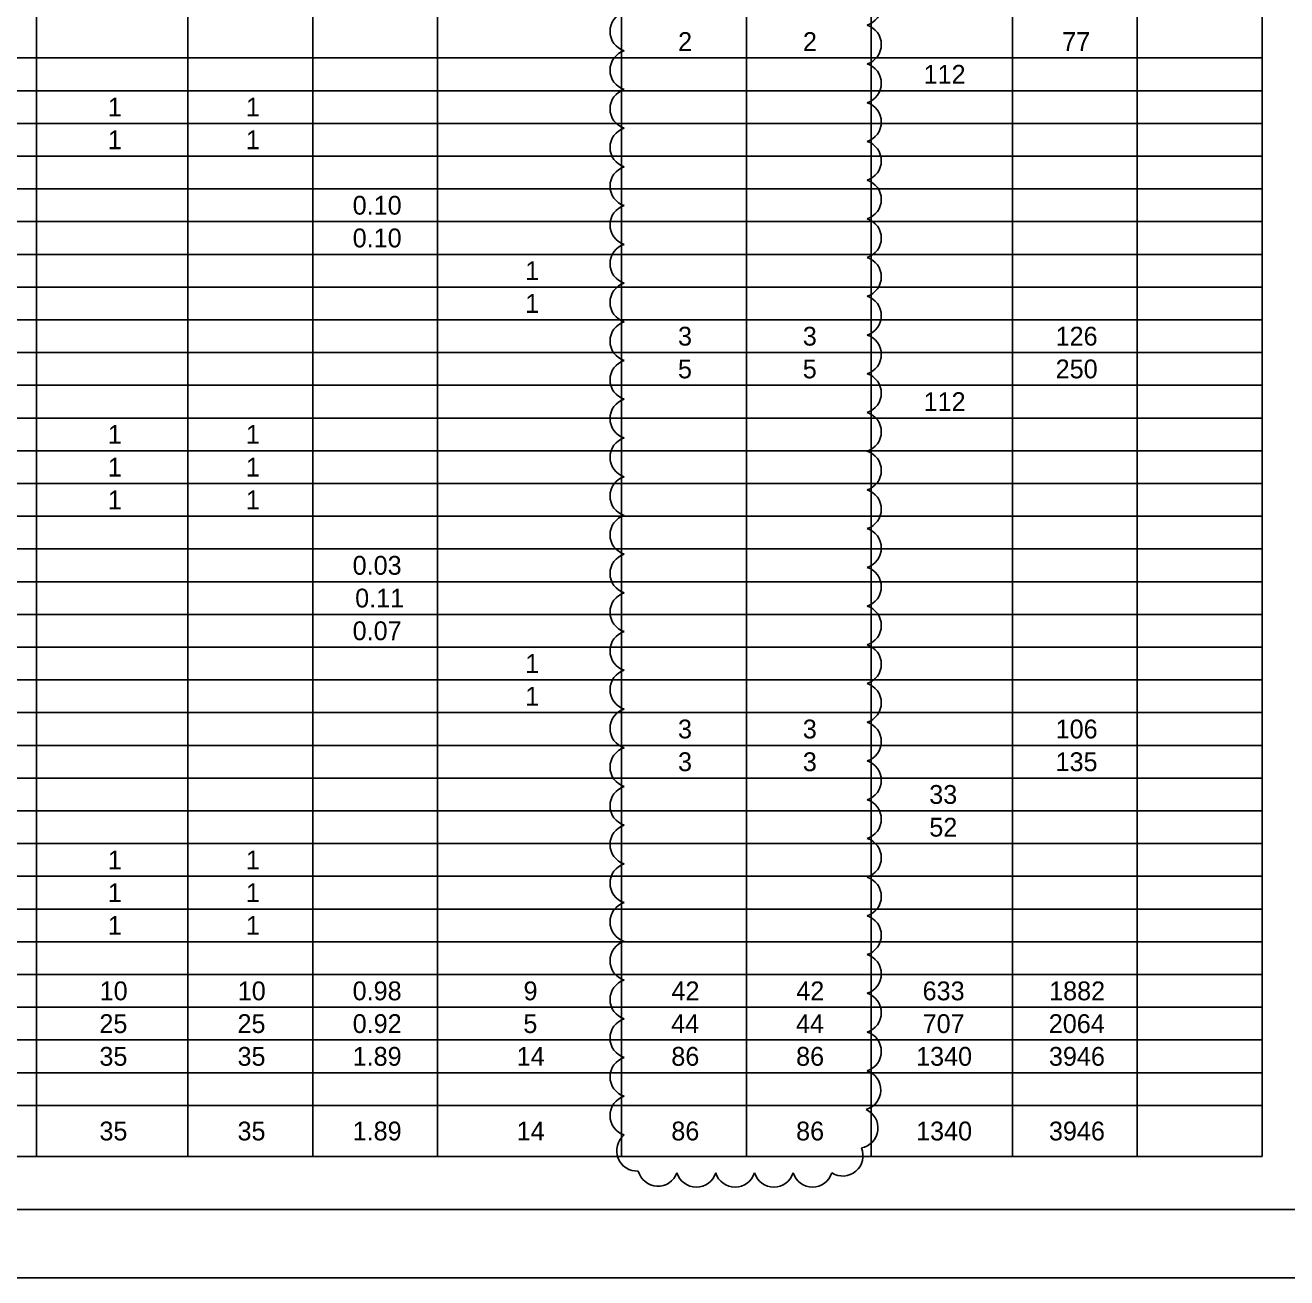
# Model space of a CAD drawing. Extents: x 0 to 35.9, y 0 to 22.
# Drawn here: x 17.78 to 27.03, y 0 to 9.18 of the extents above; entities that cross this region are included whole.
import ezdxf

# ---------------------------------------------------------------- set-up
doc = ezdxf.new("R2010")
doc.units = 0
for name, color, linetype in [('SC_Scratch2', 7, 'Continuous'), ('SH_Border', 7, 'Continuous'), ('SH_Cut_Line', 7, 'Continuous'), ('SH_Text', 7, 'Continuous')]:
    doc.layers.add(name, color=color, linetype=linetype)

msp = doc.modelspace()

# ---------------------------------------------------------------- linework, layer by layer
at = {"layer": 'SC_Scratch2'}
for centre, radius, start, end in [((23.9055, 9.3251), 0.1488, 287.5, 72.5), ((22.2141, 9.1382), 0.1488, 107.5, 252.5), ((23.9055, 9.0412), 0.1488, 287.5, 72.5), ((22.2141, 8.8543), 0.1488, 107.5, 252.5), ((23.9055, 8.7573), 0.1488, 287.5, 72.5), ((22.2141, 8.5704), 0.1488, 107.5, 252.5), ((23.9055, 8.4734), 0.1488, 287.5, 72.5), ((22.2141, 8.2865), 0.1488, 107.5, 252.5), ((23.9055, 8.1895), 0.1488, 287.5, 72.5), ((22.2141, 8.0026), 0.1488, 107.5, 252.5), ((23.9055, 7.9056), 0.1488, 287.5, 72.5), ((22.2141, 7.7187), 0.1488, 107.5, 252.5), ((23.9055, 7.6217), 0.1488, 287.5, 72.5), ((22.2141, 7.4348), 0.1488, 107.5, 252.5), ((23.9055, 7.3378), 0.1488, 287.5, 72.5), ((22.2141, 7.1509), 0.1488, 107.5, 252.5), ((23.9055, 7.0539), 0.1488, 287.5, 72.5), ((22.2141, 6.867), 0.1488, 107.5, 252.5), ((23.9055, 6.77), 0.1488, 287.5, 72.5), ((22.2141, 6.5831), 0.1488, 107.5, 252.5), ((23.9055, 6.4861), 0.1488, 287.5, 72.5), ((22.2141, 6.2991), 0.1488, 107.5, 252.5), ((23.9055, 6.2022), 0.1488, 287.5, 72.5), ((22.2141, 6.0152), 0.1488, 107.5, 252.5), ((23.9055, 5.9183), 0.1488, 287.5, 72.5), ((22.2141, 5.7313), 0.1488, 107.5, 252.5), ((23.9055, 5.6344), 0.1488, 287.5, 72.5), ((22.2141, 5.4474), 0.1488, 107.5, 252.5), ((23.9055, 5.3505), 0.1488, 287.5, 72.5), ((22.2141, 5.1635), 0.1488, 107.5, 252.5), ((23.9055, 5.0665), 0.1488, 287.5, 72.5), ((22.2141, 4.8796), 0.1488, 107.5, 252.5), ((23.9055, 4.7826), 0.1488, 287.5, 72.5), ((22.2141, 4.5957), 0.1488, 107.5, 252.5), ((23.9055, 4.4987), 0.1488, 287.5, 72.5), ((22.2141, 4.3118), 0.1488, 107.5, 252.5), ((23.9055, 4.2148), 0.1488, 287.5, 72.5), ((22.2141, 4.0279), 0.1488, 107.5, 252.5), ((23.9055, 3.9309), 0.1488, 287.5, 72.5), ((22.2141, 3.744), 0.1488, 107.5, 252.5), ((23.9055, 3.647), 0.1488, 287.5, 72.5), ((22.2141, 3.4601), 0.1488, 107.5, 252.5), ((23.9055, 3.3631), 0.1488, 287.5, 72.5), ((22.2141, 3.1762), 0.1488, 107.5, 252.5), ((23.9055, 3.0792), 0.1488, 287.5, 72.5), ((22.2141, 2.8923), 0.1488, 107.5, 252.5), ((23.9055, 2.7953), 0.1488, 287.5, 72.5), ((22.2141, 2.6084), 0.1488, 107.5, 252.5), ((23.9055, 2.5114), 0.1488, 287.5, 72.5), ((22.2141, 2.3245), 0.1488, 107.5, 252.5), ((23.9055, 2.2275), 0.1488, 287.5, 72.5), ((22.2141, 2.0406), 0.1488, 107.5, 252.5), ((23.9055, 1.9436), 0.1488, 287.5, 72.5), ((22.2141, 1.7567), 0.1488, 107.5, 252.5), ((23.9055, 1.6597), 0.1489, 287.49945, 72.49945), ((22.2141, 1.4727), 0.1488, 107.5, 252.5), ((23.9017, 1.377), 0.1488, 285.9903, 70.9903), ((22.2141, 1.1888), 0.1488, 107.5, 252.5), ((23.8813, 1.0984), 0.1488, 280.59783, 65.59783), ((22.2627, 0.931), 0.1488, 128.84345, 273.84345), ((23.7714, 0.8945), 0.1488, 237.73872, 22.73872), ((22.4167, 0.8203), 0.1488, 194.71066, 339.71066), ((22.6982, 0.8134), 0.1488, 197.5, 342.5), ((22.9821, 0.8134), 0.1488, 197.5, 342.5), ((23.2661, 0.8134), 0.1488, 197.5, 342.5), ((23.55, 0.8134), 0.1488, 197.5, 342.5)]:
    msp.add_arc(centre, radius, start, end, dxfattribs=at)
at = {"layer": 'SH_Border'}
msp.add_lwpolyline([(1.5, 21.5), (33.5, 21.5), (33.5, 0.5), (1.5, 0.5)], close=True, dxfattribs=at)
at = {"layer": 'SH_Cut_Line'}
msp.add_lwpolyline([(0, 0), (34, 0), (34, 22), (0, 22)], close=True, dxfattribs=at)
at = {"layer": 'SH_Text'}
for p, q in [((17.8605, 21.0634), (17.8605, 0.8884)), ((23.9805, 21.0634), (23.9805, 0.8884)), ((25.0155, 21.0634), (25.0155, 0.8884)), ((25.9305, 21.0634), (25.9305, 0.8884)), ((26.8455, 21.0634), (26.8455, 0.8884)), ((18.9705, 20.7034), (18.9705, 0.8884)), ((19.8855, 20.7034), (19.8855, 0.8884)), ((20.8005, 20.7034), (20.8005, 0.8884)), ((22.1505, 20.7034), (22.1505, 0.8884)), ((23.0655, 20.7034), (23.0655, 0.8884)), ((10.0305, 8.9434), (26.8455, 8.9434)), ((10.0305, 8.7034), (26.8455, 8.7034)), ((10.0305, 8.4634), (26.8455, 8.4634)), ((10.0305, 8.2234), (26.8455, 8.2234)), ((10.0305, 7.9834), (26.8455, 7.9834)), ((10.0305, 7.7434), (26.8455, 7.7434)), ((10.0305, 7.5034), (26.8455, 7.5034)), ((10.0305, 7.2634), (26.8455, 7.2634)), ((10.0305, 7.0234), (26.8455, 7.0234)), ((10.0305, 6.7834), (26.8455, 6.7834)), ((10.0305, 6.5434), (26.8455, 6.5434)), ((10.0305, 6.3034), (26.8455, 6.3034)), ((10.0305, 6.0634), (26.8455, 6.0634)), ((10.0305, 5.8234), (26.8455, 5.8234)), ((10.0305, 5.5834), (26.8455, 5.5834)), ((10.0305, 5.3434), (26.8455, 5.3434)), ((10.0305, 5.1034), (26.8455, 5.1034)), ((10.0305, 4.8634), (26.8455, 4.8634)), ((10.0305, 4.6234), (26.8455, 4.6234)), ((10.0305, 4.3834), (26.8455, 4.3834)), ((10.0305, 4.1434), (26.8455, 4.1434)), ((10.0305, 3.9034), (26.8455, 3.9034)), ((10.0305, 3.6634), (26.8455, 3.6634)), ((10.0305, 3.4234), (26.8455, 3.4234)), ((10.0305, 3.1834), (26.8455, 3.1834)), ((10.0305, 2.9434), (26.8455, 2.9434)), ((10.0305, 2.7034), (26.8455, 2.7034)), ((10.0305, 2.4634), (26.8455, 2.4634)), ((10.0305, 2.2234), (26.8455, 2.2234)), ((10.0305, 1.9834), (26.8455, 1.9834)), ((10.0305, 1.7434), (26.8455, 1.7434)), ((10.0305, 1.5034), (26.8455, 1.5034)), ((10.0305, 1.2634), (26.8455, 1.2634)), ((10.0305, 0.8884), (26.8455, 0.8884))]:
    msp.add_line(p, q, dxfattribs=at)

# ---------------------------------------------------------------- texts
for s, p in [('2', (22.5644, 8.9944)), ('2', (23.4794, 8.9944)), ('77', (25.3805, 8.9944)), ('112', (24.3643, 8.7544)), ('1', (18.3832, 8.5144)), ('1', (19.3957, 8.5144)), ('1', (18.3832, 8.2744)), ('1', (19.3957, 8.2744)), ('0.10', (20.1784, 7.7944)), ('0.10', (20.1784, 7.5544)), ('1', (21.4432, 7.3144)), ('1', (21.4432, 7.0744)), ('3', (22.5637, 6.8344)), ('3', (23.4787, 6.8344)), ('126', (25.3322, 6.8344)), ('5', (22.5632, 6.5944)), ('5', (23.4782, 6.5944)), ('250', (25.3325, 6.5944)), ('112', (24.3643, 6.3544)), ('1', (18.3832, 6.1144)), ('1', (19.3957, 6.1144)), ('1', (18.3832, 5.8744)), ('1', (19.3957, 5.8744)), ('1', (18.3832, 5.6344)), ('1', (19.3957, 5.6344)), ('0.03', (20.1781, 5.1544)), ('0.11', (20.1966, 4.9144)), ('0.07', (20.1781, 4.6744)), ('1', (21.4432, 4.4344)), ('1', (21.4432, 4.1944)), ('3', (22.5637, 3.9544)), ('3', (23.4787, 3.9544)), ('106', (25.3322, 3.9544)), ('3', (22.5637, 3.7144)), ('3', (23.4787, 3.7144)), ('135', (25.3318, 3.7144)), ('33', (24.4055, 3.4744)), ('52', (24.4061, 3.2344)), ('1', (18.3832, 2.9944)), ('1', (19.3957, 2.9944)), ('1', (18.3832, 2.7544)), ('1', (19.3957, 2.7544)), ('1', (18.3832, 2.5144)), ('1', (19.3957, 2.5144)), ('10', (18.3233, 2.0344)), ('10', (19.3358, 2.0344)), ('0.98', (20.1781, 2.0344)), ('9', (21.4313, 2.0344)), ('42', (22.5159, 2.0344)), ('42', (23.4309, 2.0344)), ('633', (24.357, 2.0344)), ('1882', (25.2844, 2.0344)), ('25', (18.3216, 1.7944)), ('25', (19.3341, 1.7944)), ('0.92', (20.1786, 1.7944)), ('5', (21.4299, 1.7944)), ('44', (22.5135, 1.7944)), ('44', (23.4285, 1.7944)), ('707', (24.3571, 1.7944)), ('2064', (25.2821, 1.7944)), ('35', (18.3216, 1.5544)), ('35', (19.3341, 1.5544)), ('1.89', (20.1782, 1.5544)), ('14', (21.381, 1.5544)), ('86', (22.5146, 1.5544)), ('86', (23.4296, 1.5544)), ('1340', (24.3093, 1.5544)), ('3946', (25.2831, 1.5544)), ('35', (18.3216, 1.0069)), ('35', (19.3341, 1.0069)), ('1.89', (20.1782, 1.0069)), ('14', (21.381, 1.0069)), ('86', (22.5146, 1.0069)), ('86', (23.4296, 1.0069)), ('1340', (24.3093, 1.0069)), ('3946', (25.2831, 1.0069))]:
    msp.add_text(s, height=0.138, dxfattribs=at).set_placement(p)

doc.saveas('drawing.dxf')
